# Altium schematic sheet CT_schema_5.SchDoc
size 205 x 258 mm
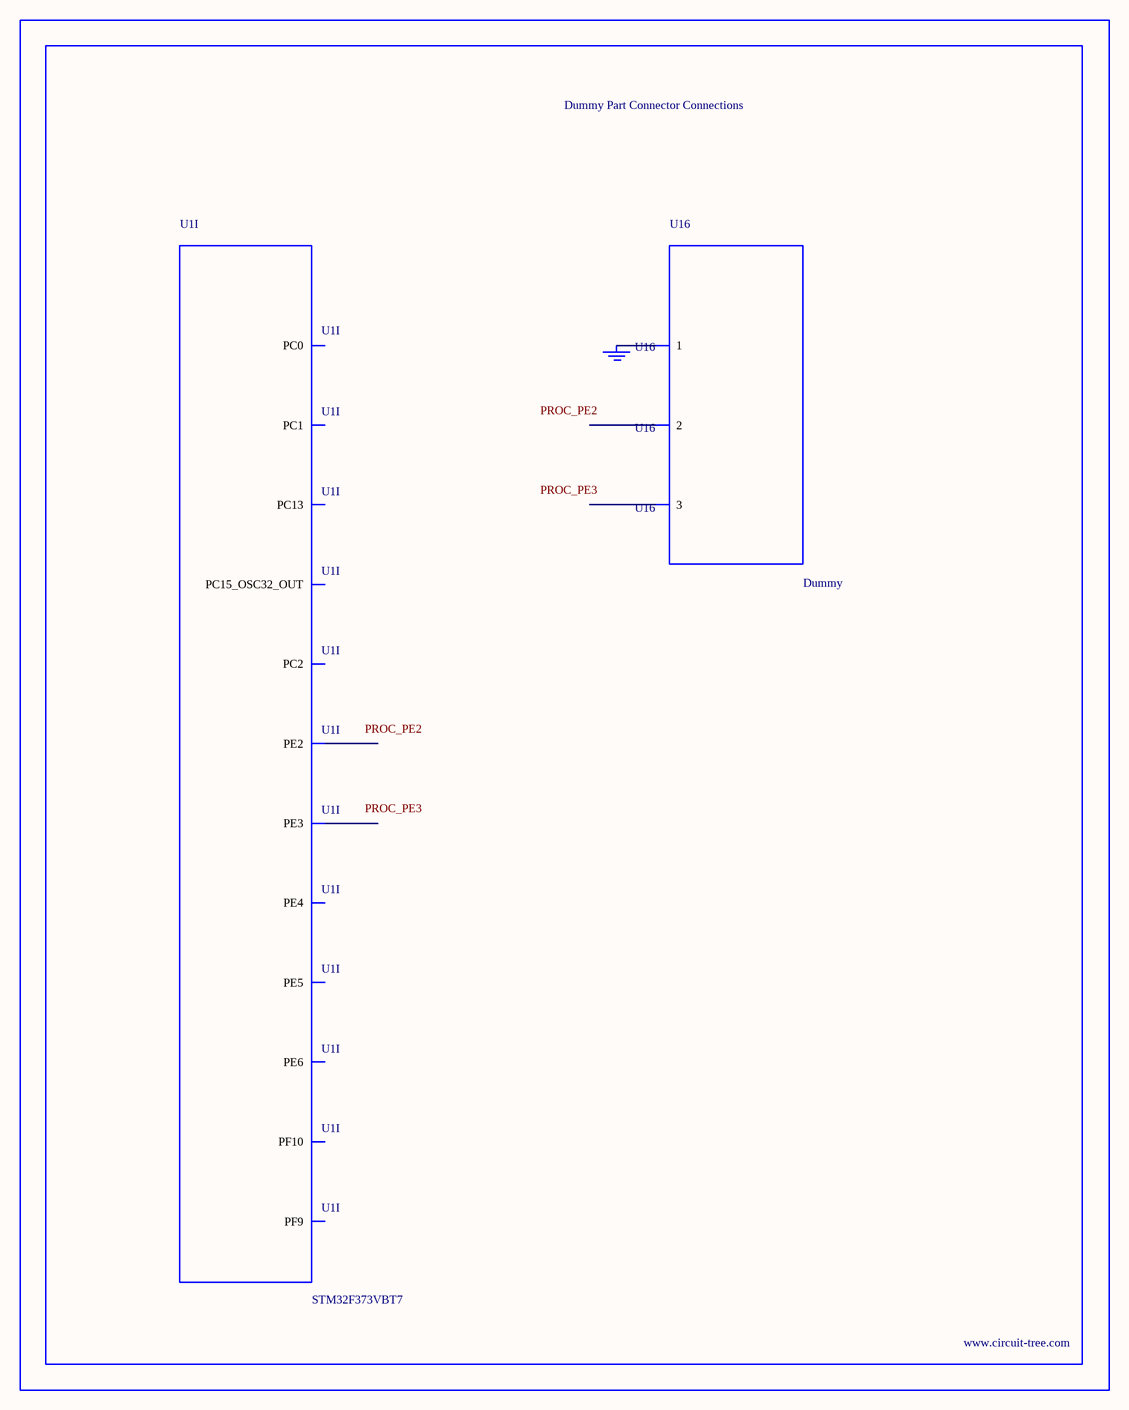
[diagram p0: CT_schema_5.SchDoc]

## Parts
BORDER4  (no value)
GND_INSTANCE_4_0  (no value)
U1  STM32F373VBT7  [LQFP100]  (part I of 9)
U16  Dummy  [DUMMY_PACKAGE_163]

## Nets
NetGND_INSTANCE_4_0_0: GND_INSTANCE_4_0.0(GND) U16.1

Not connected (* = marked no-connect by the designer): U1 1(PE2) 2(PE3) 3(PE4) 4(PE5) 5(PE6) 7(PC13) 9(PC15_OSC32_OUT) 10(PF9) 11(PF10) 15(PC0) 16(PC1) 17(PC2); U16 2 3

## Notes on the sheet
- Labels drawn without touching a wire or pin: PROC_PE2, PROC_PE3

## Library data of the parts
BORDER4 = BORDER_PAGE4
GND_INSTANCE_4_0 = GND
